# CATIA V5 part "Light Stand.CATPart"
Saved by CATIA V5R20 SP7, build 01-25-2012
Part number: Light Stand
Bounding box of the stored display mesh (mm): x -15 to 15, y -370 to 370, z -15 to 25
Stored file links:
  E:\#03 University\#02 영남 이공대\#01 2021\#02 여름 방학\#01 Documents\K-Move Page02 ASD01\Light Stand.CATPart

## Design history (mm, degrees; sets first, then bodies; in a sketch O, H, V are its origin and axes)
Set1 "Reference Data"
  Point1 "Center Point": (0, 0, 0)
Body1 (main body)
  Body2
    Sketch1 on zx-plane, origin (0, 0, 0), H (-1, 0, 0), V (0, 0, 1)
      circle A1 centre (0, 0) radius 15
      radius A1 = 15
    Pad1: profile Sketch1, direction (0, 1, 0), length 370, mirrored extent
  Assemble1: tool Body2
  Body3
    Sketch2 on xy-plane, origin (0, 0, 0), H (0, 1, 0), V (-1, 0, 0)
      circle A1 centre (290, 0) radius 7.5
      point P1 (290, 0)
      radius A1 = 7.5
      distance V P1 = 290
      coincidence: P1 H
    Pad2: profile Sketch2, direction (0, 0, 1), length 25
    Mirror1: of the body so far, about zx-plane
  Assemble2: tool Body3
  Body4 "Hole Body"
    Sketch3 on xy-plane, origin (0, 0, 0), H (0, 1, 0), V (-1, 0, 0)
      circle A1 centre (80, 0) radius 10
      point P1 (80, 0)
      distance V P1 = 80
      radius A1 = 10
      coincidence: P1 H
    Sketch4 on xy-plane, origin (0, 0, 0), H (0, 1, 0), V (-1, 0, 0)
      circle A1 centre (-80, 0) radius 10
      point P1 (-80, 0)
      radius A1 = 10
      distance P1 V = 80
      coincidence: P1 H
    Pad3: profile Sketch3, direction (0, 0, -1), length 30, opposite side length 5
    Pad4: profile Sketch4, direction (0, 0, -1), length 30, opposite side length 5
  Remove1: tool Body4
